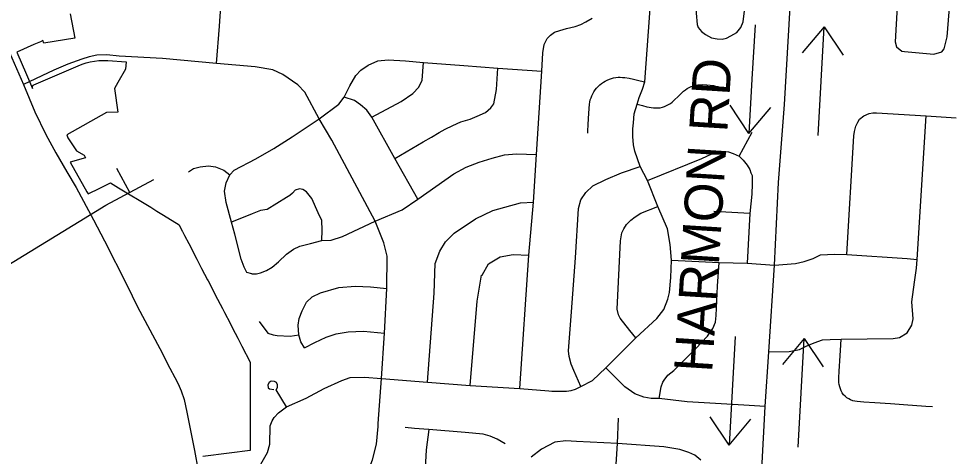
# Model space of a CAD drawing. Extents: x 1880545 to 1948545, y 79309 to 723051.
# Drawn here: x 1888580 to 1895460, y 698000 to 701215 of the extents above; entities that cross this region are included whole.
import ezdxf

# ---------------------------------------------------------------- set-up
doc = ezdxf.new("R2010")
doc.units = 0
for name, color, linetype in [('GM_X_Corporation', 7, 'Continuous'), ('GM_X_State_Route', 7, 'Continuous'), ('GM_X_Township_Road', 7, 'Continuous'), ('SH_Text', 7, 'Continuous')]:
    doc.layers.add(name, color=color, linetype=linetype)

msp = doc.modelspace()

# ---------------------------------------------------------------- linework, layer by layer
at = {"layer": 'GM_X_Corporation'}
msp.add_lwpolyline([(1888957.9, 701250.8), (1888992.9, 701070.9), (1888765.2, 701036.1), (1888757.5, 701053.9), (1888739, 701045.9), (1888690.1, 701024.6), (1888689.9, 701024.6), (1888564.9, 700970.2), (1888636.6, 700805.4), (1888681.5, 700702.8), (1888680.5, 700705.8), (1888679.9, 700708.9), (1888679.9, 700712), (1888680.3, 700715.1), (1888681.2, 700718.1), (1888682.6, 700720.9), (1888684.4, 700723.5), (1888686.6, 700725.8), (1888689.1, 700727.6), (1888691.9, 700729.1), (1889015.6, 700869.8), (1889044.8, 700881.3), (1889074.7, 700890.8), (1889105.2, 700898.2), (1889136.1, 700903.6), (1889168.6, 700907), (1889201.3, 700908.2), (1889233.9, 700907), (1889368.6, 700897.2), (1889364.7, 700843.1), (1889308, 700746), (1889282.6, 700702.6), (1889306.3, 700528.7), (1889225.2, 700526.7), (1888932.5, 700360.4), (1888940.2, 700339.4), (1889003.4, 700244.1), (1889060.2, 700211.1), (1889070.9, 700191.6), (1888956.4, 700160.1), (1889079.5, 699943.1), (1889088.4, 699927.5), (1889114.7, 699939.9), (1889149.9, 699957.2), (1889170.3, 699967.1), (1889254.1, 700008.1), (1889312.2, 699973), (1889548.4, 699830.1), (1889593.7, 699801.7), (1889643.4, 699770.6), (1889757.4, 699699.1), (1889768, 699678.7), (1889776.6, 699662.1), (1889780.4, 699654.6), (1889782.4, 699650.8), (1889797, 699622.5), (1889828.4, 699561.9), (1889874.2, 699473.2), (1889875.4, 699470.9), (1889886.7, 699448.9), (1889922.4, 699379.9), (1889966, 699295.5), (1889969.4, 699289), (1890038.7, 699154.9), (1890057.8, 699117.8), (1890074.7, 699085.2), (1890090.3, 699054.9), (1890130.7, 698976.8), (1890149.7, 698940.1), (1890187.4, 698867.1), (1890217, 698809.8), (1890278.1, 698691.6), (1890279, 698642.1), (1890278.6, 698473.9), (1890278.5, 698423.9), (1890278.4, 698371.7), (1890278.2, 698280.1), (1890278, 698146.4), (1890277.9, 698042), (1890124, 698023.3), (1889929.9, 697998.8)], dxfattribs=at)
at = {"layer": 'GM_X_State_Route'}
msp.add_lwpolyline([(1888461.2, 701084.8), (1888613.9, 700732.4), (1888697.6, 700530.6), (1888779, 700363.3), (1888852.6, 700229.5), (1888934, 700090.1), (1889000.8, 699974.2), (1889128.4, 699738.1), (1889210.5, 699581.7), (1889373.3, 699259.5), (1889452.4, 699098.9), (1889615.2, 698791.2), (1889689.9, 698646.2), (1889725.6, 698579.3), (1889750.2, 698532.5), (1889772.4, 698481.2), (1889793.6, 698416.5), (1889813.7, 698324), (1889870.6, 698041.8), (1889897.7, 697895.3)], dxfattribs=at)
at = {"layer": 'GM_X_Township_Road'}
for p, q in [((1893867.3, 700205.7), (1893962.6, 700380.7)), ((1893944.8, 699784.7), (1893680.4, 699798)), ((1894025, 699411.8), (1894125, 699405)), ((1894056.5, 698365.9), (1893901, 698375.3))]:
    msp.add_line(p, q, dxfattribs=at)
for points in [[(1893877.7, 695527.3), (1893984.5, 697013.8), (1893988, 697069.3), (1894056.5, 698365.9), (1894084.6, 698766.4), (1894125, 699405), (1894154.8, 700011.9), (1894198.1, 700583.6), (1894255.6, 701555.1), (1894282.3, 701969.7), (1894290.1, 702131.5), (1894337.5, 702466), (1894370.9, 702994.9), (1894386.8, 703208.7), (1894398.1, 703430.9), (1894398.5, 703471.9), (1894394.6, 703524.9)], [(1895128.1, 701814.3), (1895054.9, 701753), (1894997.2, 701700.6), (1894974.6, 701662.5), (1894959.7, 701634.6), (1894952.5, 701603.9), (1894947.8, 701577.4), (1894945.4, 701540.8), (1894961.4, 701482.4), (1895007.3, 701359.4), (1895018, 701333.3), (1895024.4, 701260.8), (1895018.6, 701175.5), (1895010.8, 701045.5), (1895020.5, 701008.7), (1895061.2, 700975.8), (1895080.6, 700973.8), (1895295.8, 700954.4), (1895354, 700971.9), (1895371.4, 700993.2), (1895392.8, 701080.5), (1895444.7, 701725.4)], [(1892889.3, 698649.8), (1892992.7, 698755.9), (1893108, 698869.2), (1893261.6, 699011.3), (1893312.8, 699077.5), (1893342.8, 699154.1), (1893356.1, 699204), (1893366.1, 699313.8), (1893371, 699440.3), (1893361.3, 699556), (1893341, 699671.2), (1893270.6, 699833.8), (1893194.7, 700026.1), (1893139.2, 700129.1), (1893101.4, 700240.7), (1893091.8, 700289), (1893087, 700349.3), (1893087, 700404.8), (1893090.6, 700449.4), (1893096.6, 700515.8), (1893118.1, 700587.5), (1893132.9, 700635.2), (1893156.9, 700696.3), (1893173.7, 700750.7), (1893238.5, 701627.5)], [(1893571.5, 701600.8), (1893564.5, 701505.7), (1893555.1, 701363.7), (1893550.4, 701255.7), (1893557.4, 701171.2), (1893566.8, 701151.3), (1893590.3, 701120.7), (1893619.6, 701099.6), (1893663, 701073.8), (1893705.3, 701066.7), (1893742.8, 701065.6), (1893774.5, 701072.6), (1893805, 701087.9), (1893848.4, 701112.5), (1893877.8, 701151.3), (1893895.4, 701191.2), (1893905.9, 701273.3), (1893913, 701388.4), (1893922.4, 701577.4)], [(1890030.7, 700886.7), (1890054.1, 701160), (1890063.1, 701305.2)], [(1892257.7, 698497.9), (1892323, 699477.3), (1892357.6, 699866.4), (1892379.8, 700217.8), (1892419.5, 700830.3), (1892426.3, 700964), (1892435.7, 701025.8), (1892457.1, 701068.8), (1892481.3, 701094.3), (1892510.8, 701117.1), (1892549.8, 701129.2), (1892599.5, 701142.7), (1892662.6, 701158.8), (1892704.2, 701172.2), (1892741.8, 701192.4), (1892787.4, 701219.2)], [(1891218.7, 698240.3), (1891242.4, 698570.2), (1891263, 698905), (1891282.2, 699232.5), (1891282.7, 699470.7), (1891260.2, 699567.6), (1891195.9, 699727.8), (1890877.3, 700322.5), (1890784.9, 700479.9), (1890679.8, 700674.1), (1890628.4, 700727.8), (1890518.3, 700805.2), (1890445.2, 700838.6), (1890315.5, 700861), (1890030.7, 700886.7), (1889636.1, 700921.7), (1889316.2, 700940.4), (1889226.8, 700948.3), (1889152.5, 700945.9), (1889096.5, 700935.9), (1889042.4, 700917.8), (1888939.4, 700881.5), (1888838.7, 700837), (1888613.9, 700732.4)], [(1890762.8, 700465.2), (1890784.9, 700479.9), (1890927.8, 700587.8), (1890967.5, 700638), (1891009.2, 700721.6), (1891053.1, 700796.8), (1891090.7, 700836.5), (1891145.1, 700874.2), (1891214, 700905.5), (1891291.3, 700911.8), (1891418.8, 700905.5), (1891550.4, 700893), (1891847, 700872.1), (1892095.7, 700851.2), (1892419.5, 700830.3)], [(1891170.1, 700491.6), (1891385.3, 700606.6), (1891473.1, 700665.1), (1891517, 700711.1), (1891539.9, 700763.4), (1891550.4, 700893)], [(1891340.9, 700187.6), (1891547.7, 700310.7), (1891607.8, 700344.2), (1891666.1, 700379.6), (1891710.2, 700404.3), (1891765, 700429), (1891825, 700457.3), (1891892.1, 700476.7), (1891945.1, 700498), (1892005.2, 700524.5), (1892044, 700559.8), (1892067, 700589.8), (1892086.4, 700695.8), (1892095.7, 700851.2)], [(1892757.2, 700373.8), (1892755.8, 700388.7), (1892758.2, 700438), (1892764.1, 700520.1), (1892768.2, 700585.8), (1892770.5, 700602.1), (1892774.3, 700618.1), (1892779.4, 700633.8), (1892785.3, 700649.1), (1892792.5, 700663.9), (1892800.9, 700678.1), (1892810.4, 700691.5), (1892820.8, 700704.3), (1892831.9, 700716.4), (1892843.9, 700727.8), (1892856.5, 700738.3), (1892870, 700747.8), (1892884.1, 700756.1), (1892898.9, 700763.4), (1892914.1, 700769.9), (1892929.6, 700775.5), (1892945.4, 700779.9), (1892961.5, 700782.8), (1892977.9, 700784.3), (1892994.3, 700784.5), (1893010.8, 700783.7), (1893027.4, 700782.1), (1893060, 700777.3), (1893092.2, 700770.7), (1893140.2, 700758.9), (1893173.7, 700750.7)], [(1893118.1, 700587.5), (1893157.2, 700577), (1893189.1, 700568.5), (1893205.2, 700565), (1893221.4, 700562.2), (1893237.8, 700560.3), (1893254.2, 700559.3), (1893270.7, 700559.4), (1893287.1, 700561.2), (1893303.2, 700564.7), (1893318.8, 700569.7), (1893334.1, 700576), (1893348.7, 700583.6), (1893362.6, 700592.4), (1893375.8, 700602.3), (1893388.2, 700613.1), (1893423, 700648.2), (1893446.4, 700671.4), (1893458.7, 700682.4), (1893471.7, 700692.6), (1893485.4, 700701.6), (1893500, 700709.3), (1893515.1, 700715.8), (1893530.7, 700721.2), (1893546.6, 700725.5), (1893562.8, 700728.5), (1893579.1, 700730), (1893595.6, 700730.4), (1893628.5, 700728.5), (1893677.7, 700723.1), (1893693.9, 700720.4), (1893709.9, 700716.7), (1893725.7, 700712), (1893741.2, 700706.2), (1893753.5, 700699.7)], [(1891509.3, 699887.9), (1891340.9, 700187.6), (1891170.1, 700491.6), (1891134.6, 700541.8), (1891088.6, 700581.5), (1891042.7, 700612.9), (1890967.5, 700638)], [(1890290.3, 699339.7), (1890254.7, 699351.1), (1890233.1, 699389.3), (1890211.5, 699449.1), (1890167, 699632.2), (1890141.6, 699720), (1890103.4, 699863.7), (1890090.7, 699948.3), (1890103.4, 700009.3), (1890128.9, 700067.8), (1890161.9, 700100.9), (1890319.6, 700184.9), (1890451.8, 700261.2), (1890586.5, 700347.6), (1890762.8, 700465.2)], [(1894084.6, 698766.4), (1894234.2, 698769.7), (1894309.1, 698784.7), (1894357.3, 698809.6), (1894417.2, 698833), (1894477.1, 698854.6), (1894535.5, 698856.9), (1894615.5, 698859), (1894995.5, 698864.1), (1895043.8, 698872.6), (1895099.1, 698907.2), (1895134.2, 698962), (1895143.5, 699010.3), (1895133.4, 699134), (1895152.1, 699277.9), (1895167.8, 699381), (1895172.9, 699444.3), (1895240, 700501.6)], [(1894656.8, 699481.9), (1894709.1, 700353.1), (1894712.5, 700385.9), (1894722.2, 700425.9), (1894736.3, 700455.6)], [(1894736.3, 700455.6), (1894750.5, 700475.9), (1894781.9, 700502.1), (1894819.9, 700517.9), (1894847.1, 700523.1), (1894873.6, 700523.9), (1895240, 700501.6), (1895459.5, 700486.7)], [(1890290.3, 699339.7), (1890324.7, 699341), (1890355.1, 699348.6), (1890397.1, 699365.1), (1890439.1, 699388), (1890487.4, 699428.7), (1890544.6, 699485.9), (1890596.7, 699520.3), (1890643.8, 699543.2), (1890721.3, 699563.5), (1890803.9, 699585.1), (1890872.6, 699586.4), (1890955.2, 699615.7), (1891195.9, 699727.8), (1891393, 699811), (1891509.3, 699887.9), (1891773.9, 700075.7), (1891863.7, 700123.8), (1891959.9, 700161.4), (1892053.9, 700190.7), (1892145.8, 700215.7), (1892231.5, 700222), (1892379.8, 700217.8)], [(1893194.7, 700026.1), (1893591.5, 700188.7), (1893667.1, 700221.4), (1893711.7, 700235.9), (1893744.3, 700239.5), (1893788.9, 700235.9), (1893822.7, 700225), (1893867.3, 700205.7), (1893896.3, 700175.5), (1893925.2, 700139.3), (1893944.5, 700106.7), (1893951.8, 700083.4), (1893961.4, 700062.1), (1893961.4, 700001.8), (1893959, 699925.8), (1893944.8, 699784.7), (1893924.9, 699418.6)], [(1889825.1, 700090.5), (1889862.1, 700114.2), (1889911.5, 700127.5), (1889972.2, 700134.8), (1890024.6, 700126.5), (1890084.3, 700101.8), (1890128.9, 700067.8)], [(1892705.6, 698513), (1892653.2, 698629.2), (1892634.1, 698677.2), (1892619.6, 698733.8), (1892613.8, 698773.5), (1892635.7, 699061.8), (1892666.5, 699457.7), (1892687.5, 699820.5), (1892704.1, 699883.7), (1892740.7, 699937), (1892793.9, 699986.9), (1892888.7, 700032.9), (1893003.8, 700081.7), (1893139.2, 700129.1)], [(1890803.9, 699585.1), (1890807.7, 699661.5), (1890803.9, 699731.4), (1890778.5, 699788.7), (1890730.2, 699894.2), (1890692.1, 699943.8), (1890665.3, 699960.3), (1890639.9, 699965.4), (1890609.4, 699954), (1890589.6, 699933), (1890568.9, 699916.5), (1890545.9, 699901.8), (1890403.5, 699812.8), (1890353.9, 699806.5), (1890292.9, 699781), (1890141.6, 699720)], [(1891579.3, 698543.9), (1891627.5, 699197.4), (1891635.5, 699416), (1891670.7, 699507.2), (1891712.8, 699575.9), (1891774.1, 699639.9), (1891931.3, 699743.8), (1892059.2, 699805.2), (1892147.1, 699829.1), (1892261.7, 699861.1), (1892357.6, 699866.4)], [(1893108, 698869.2), (1893063.8, 698923), (1892993.4, 699013.6), (1892981.2, 699038.2), (1892971.6, 699080.5), (1892995.7, 699581.8), (1893006.5, 699641.4), (1893021.4, 699671.2), (1893040.4, 699702.4), (1893071.5, 699734.9), (1893102.7, 699757.9), (1893146, 699785), (1893270.6, 699833.8)], [(1891892.2, 698519.5), (1891945, 699139.6), (1891976.6, 699330.7), (1891981, 699331.3), (1892027.2, 699413.3), (1892112.5, 699464), (1892208.4, 699482.6), (1892323, 699477.3)], [(1893278.9, 698423.5), (1893294.2, 698510), (1893305.7, 698544.5), (1893317.2, 698558), (1893344.1, 698596.4), (1893388.3, 698629.1), (1893547.7, 698790.4), (1893634.1, 698882.7), (1893674.4, 698938.4), (1893693.7, 698986), (1893698.7, 699034.3), (1893708.7, 699250.6), (1893720.3, 699423.6)], [(1893371, 699440.3), (1893720.3, 699423.6), (1893924.9, 699418.6), (1894025, 699411.8)], [(1894125, 699405), (1894280.8, 699417), (1894344, 699430.3), (1894410.5, 699453.6), (1894463.8, 699478.6), (1894566.1, 699483.9), (1894656.8, 699481.9), (1895099, 699452.3), (1895172.9, 699444.3)], [(1890676.3, 698797.2), (1890649.6, 698840.5), (1890634.3, 698890.9), (1890631.3, 698964.1), (1890638.9, 699012.9), (1890658.7, 699069.3), (1890692.2, 699131.8), (1890733.4, 699171.5), (1890794.4, 699200.4), (1890930, 699238.6), (1891049, 699250.8), (1891161.8, 699244.7), (1891282.2, 699232.5)], [(1890344.7, 698990), (1890407.2, 698904.6), (1890448.3, 698890.9), (1890475.8, 698886.3), (1890571.8, 698883.2), (1890634.3, 698890.9)], [(1890676.3, 698797.2), (1890751.9, 698836.2), (1890836.7, 698875.2), (1890910.1, 698898.1), (1890997.1, 698914.2), (1891109.4, 698918.7), (1891263, 698905)], [(1895285.2, 698361.9), (1895236.3, 698364.8), (1895073.6, 698377.2), (1894975.9, 698383.9), (1894861.9, 698391.5), (1894780.6, 698397.1), (1894731.8, 698401.3), (1894715.7, 698403.9), (1894699.9, 698407.9), (1894684.7, 698413.6), (1894670.2, 698421), (1894656.5, 698430), (1894643.9, 698440.3), (1894632.8, 698452.2), (1894623.2, 698465.4), (1894615.3, 698479.7), (1894609.1, 698494.8), (1894604.2, 698510.4), (1894600.6, 698526.3), (1894598.4, 698542.4), (1894597.4, 698558.7), (1894597.5, 698575), (1894599.8, 698624), (1894608.9, 698737.9), (1894613.3, 698819.3), (1894615.5, 698859)], [(1892470.7, 698480.9), (1892492, 698479.2), (1892598.8, 698477.3), (1892632.6, 698483), (1892666.3, 698492.4), (1892705.6, 698513), (1892789.9, 698556.1), (1892889.3, 698649.8)], [(1893901, 698375.3), (1893486.2, 698400.5), (1893278.9, 698423.5), (1893221.2, 698423.5), (1893167.5, 698435.1), (1893100.3, 698458.1), (1893027.3, 698510), (1892889.3, 698649.8)], [(1890544.7, 698361.7), (1890468.6, 698488.4), (1890479.2, 698506.1), (1890479.2, 698525.6), (1890470.4, 698540.6), (1890456.2, 698549.5), (1890433.2, 698552.1), (1890417.2, 698542.4), (1890407.5, 698525.6), (1890410.2, 698503.5), (1890420.8, 698494.6), (1890451.8, 698490.1)], [(1890544.7, 698361.7), (1890690, 698425.8), (1890820.7, 698496.8), (1890951.3, 698556.5), (1891013.2, 698579.4), (1891116.3, 698581.7), (1891242.4, 698570.2), (1891579.3, 698543.9), (1891892.2, 698519.5), (1892257.7, 698497.9), (1892470.7, 698480.9)], [(1890307.3, 697600.3), (1890289.3, 697724.8), (1890292.4, 697777.6), (1890311.9, 697843.2), (1890356.2, 697940.6), (1890405.8, 698027.4), (1890423.5, 698089.8), (1890425.2, 698223.6), (1890439.4, 698259), (1890454.5, 698283.8), (1890486.3, 698319.2), (1890544.7, 698361.7)], [(1892121.9, 697049.3), (1892179, 697100.1), (1892229.7, 697138.2), (1892297.4, 697161.5), (1892375.7, 697172.1), (1892432.8, 697185), (1892552.1, 697239.7), (1892737.8, 697327.7), (1892855.1, 697388.4), (1892882.5, 697411.8), (1892913.8, 697450.9), (1892931.4, 697488.1), (1892939.2, 697552.6), (1892952.9, 697748.2), (1892974.4, 698092.5), (1892982.2, 698280.2)], [(1889968, 697532.7), (1890152.2, 697570.7), (1890307.3, 697600.3), (1890386.7, 697613.8), (1890487.1, 697618.4), (1890582.2, 697628.7), (1890723.9, 697621.5), (1890815.1, 697638.3), (1890882.3, 697662.4), (1890995.2, 697741.6), (1891115.2, 697854.5), (1891150.7, 697909.9), (1891175.9, 697974.1), (1891205.7, 698088.7), (1891217.2, 698219.4), (1891218.7, 698240.3)], [(1892148.5, 698090.2), (1892091.7, 698125.8), (1892039.1, 698147.5), (1891987.5, 698161.3), (1891856, 698173.1), (1891589.5, 698195.5), (1891585.7, 698195.8), (1891483.6, 698204.7), (1891415.2, 698211.6)], [(1891589.5, 698195.5), (1891569.4, 698046.2), (1891559.4, 697866.8)], [(1893585.7, 697969.8), (1893541.8, 698008.9), (1893497.8, 698028.4), (1893431.8, 698050.4), (1893314.6, 698070), (1892974.4, 698092.5), (1892673.3, 698108.5), (1892595.1, 698114), (1892514.9, 698102.2), (1892417.2, 698051.4), (1892340.9, 697994.2)]]:
    msp.add_lwpolyline(points, dxfattribs=at)
at = {"layer": 'SH_Text'}
for p, q in [((1893983.1, 701169.6), (1893960.6, 700770.2)), ((1894490.2, 701154.7), (1894329.4, 700963.3)), ((1894468.2, 700755.3), (1894490.2, 701154.7)), ((1894490.2, 701154.7), (1894629, 700946.8)), ((1893960.6, 700770.2), (1893938.2, 700370.8)), ((1894446.1, 700355.9), (1894468.2, 700755.3)), ((1893938.2, 700370.8), (1893799.6, 700578.9)), ((1893938.2, 700370.8), (1894099.2, 700562.1)), ((1889394.7, 699939), (1889299.7, 700115)), ((1889218.8, 699844), (1889570.7, 700034.1)), ((1885733.6, 697710.2), (1889218.8, 699844)), ((1893837.2, 698879.5), (1893814.7, 698480.1)), ((1894344.4, 698864.7), (1894183.6, 698673.2)), ((1894322.3, 698465.3), (1894344.4, 698864.7)), ((1894344.4, 698864.7), (1894483.1, 698656.7)), ((1893814.7, 698480.1), (1893792.3, 698080.8)), ((1894300.3, 698065.9), (1894322.3, 698465.3)), ((1893792.3, 698080.8), (1893653.8, 698288.9)), ((1893792.3, 698080.8), (1893953.3, 698272))]:
    msp.add_line(p, q, dxfattribs=at)

# ---------------------------------------------------------------- texts
msp.add_text('HARMON RD', height=280, rotation=86.40079, dxfattribs=at).set_placement((1893667.8, 698611.5))

doc.saveas('drawing.dxf')
